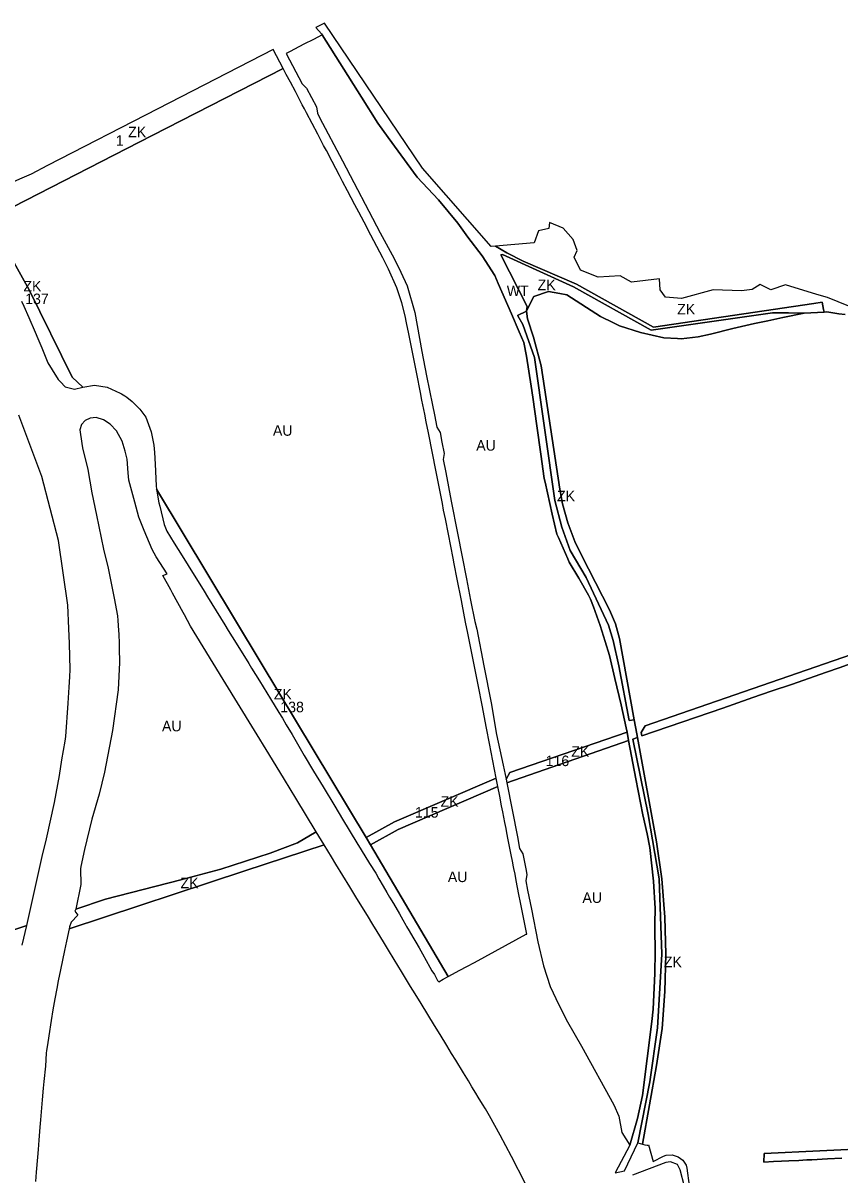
# Model space of a CAD drawing. Extents: x -521939 to -516426, y -1197857 to -1189551.
# Drawn here: x -520821 to -520047, y -1190643 to -1189551 of the extents above; entities that cross this region are included whole.
import ezdxf

# ---------------------------------------------------------------- set-up
doc = ezdxf.new("R2010")
doc.units = 0
for name, color, linetype in [('90640013', 7, 'Continuous'), ('90670013', 7, 'Continuous'), ('90710013', 7, 'Continuous'), ('90710023', 7, 'Continuous'), ('90750013', 7, 'Continuous'), ('90760013', 7, 'Continuous'), ('ID_navrh', 7, 'Continuous')]:
    doc.layers.add(name, color=color, linetype=linetype)

msp = doc.modelspace()

# ---------------------------------------------------------------- linework, layer by layer
at = {"layer": '90640013'}
msp.add_lwpolyline([(-520249.16, -1190222.86), (-520247.81, -1190230.86), (-520240.81, -1190266.98), (-520234.02, -1190301.08), (-520229.98, -1190319.14), (-520227.7, -1190332.07), (-520224.06, -1190364.1), (-520222.52, -1190389.87), (-520222.95, -1190404.31), (-520222.72, -1190408.83), (-520222.42, -1190430.62), (-520222.94, -1190451.62), (-520224.3, -1190485.28), (-520225.71, -1190497.03), (-520234.45, -1190567.4), (-520239.1, -1190588.96), (-520246.6, -1190614.37), (-520260.36, -1190640.4), (-520251.47, -1190638.58), (-520245.17, -1190625.39), (-520238.87, -1190612.21), (-520227.65, -1190554.34), (-520220.13, -1190502.96), (-520216.05, -1190433.23), (-520218.73, -1190361.97), (-520229.18, -1190300.77), (-520243.7, -1190229.44), (-520239.31, -1190227.93), (-520239.93, -1190224.53), (-520242.33, -1190211.29), (-520247.17, -1190211.76), (-520256.93, -1190159.92), (-520262.41, -1190136.08), (-520266.75, -1190121.3), (-520287.85, -1190076.23), (-520303.14, -1190050.73), (-520311.05, -1190028.55), (-520317.52, -1190003.34), (-520336.9, -1189867.83), (-520347.8, -1189836.47), (-520352.51, -1189828.3), (-520352.79, -1189827.82), (-520344.45, -1189823.72), (-520344.5, -1189823.36), (-520344.13, -1189821.36), (-520343.76, -1189819.36), (-520368.53, -1189770.54), (-520367.2, -1189770.07), (-520299.91, -1189800.71), (-520226.2, -1189841.93), (-520111.39, -1189825.49), (-520096.34, -1189825.53), (-520081.3, -1189825.57), (-520062.45, -1189824.69), (-520063.06, -1189822.2), (-520064.26, -1189815.41), (-520072.16, -1189816.57), (-520223.99, -1189839), (-520296.88, -1189798.09), (-520347.45, -1189776.56), (-520363.05, -1189768.61), (-520373.58, -1189762.19), (-520377.81, -1189762.57), (-520442.97, -1189688.4), (-520535.72, -1189550.71), (-520541.98, -1189553.93), (-520543.9, -1189554.92), (-520538.7, -1189561.06), (-520538.07, -1189562.04), (-520500.57, -1189620.82), (-520485.08, -1189645.55), (-520475.34, -1189659.1), (-520448.02, -1189696.82), (-520427.67, -1189718.16), (-520409.45, -1189740.47), (-520399.82, -1189753.72), (-520386.38, -1189771.5), (-520374.37, -1189789.92), (-520371.11, -1189797.47), (-520358.66, -1189826.35), (-520351.31, -1189843.38), (-520346.91, -1189853.63), (-520344.39, -1189866.49), (-520339.95, -1189895.05), (-520338.49, -1189905.37), (-520334.63, -1189932.46), (-520330.78, -1189959.3), (-520327.48, -1189982.3), (-520326.69, -1189985.96), (-520320.21, -1190016.34), (-520315.66, -1190035.24), (-520314.17, -1190038.32), (-520305.36, -1190058.45), (-520303.92, -1190061.74), (-520294.93, -1190077), (-520285.54, -1190093.03), (-520283.85, -1190096.73), (-520280.91, -1190104.08), (-520274.49, -1190121.75), (-520269.75, -1190136.9), (-520265.74, -1190150.19), (-520260.67, -1190171.89), (-520254.69, -1190197.09), (-520249.83, -1190218.86), (-520249.16, -1190222.86)], dxfattribs=at)
at = {"layer": '90670013'}
msp.add_lwpolyline([(-520194.85, -1190653.37), (-520198.74, -1190637.77), (-520201.28, -1190632.52), (-520208.07, -1190630.09), (-520212.3, -1190630.74), (-520243.84, -1190642.67)], dxfattribs=at)
at = {"layer": '90710013'}
for points in [[(-520038.96, -1189819.12), (-520059.38, -1189810.98), (-520069.51, -1189807.88), (-520099.05, -1189798.82), (-520113.06, -1189803.55), (-520122.95, -1189798.51), (-520130.63, -1189803.21), (-520140.61, -1189804.59), (-520167.44, -1189803.44), (-520197.6, -1189811.81), (-520212.85, -1189810.43), (-520217.67, -1189803.44), (-520218.36, -1189793.23), (-520244.78, -1189796.37), (-520255.75, -1189790.34), (-520276.62, -1189791.67), (-520293.27, -1189784.91), (-520299.12, -1189772.69), (-520296.49, -1189766.45), (-520300.08, -1189755.79), (-520309.79, -1189745.12), (-520322.5, -1189739.84), (-520323.33, -1189745.6), (-520333.04, -1189747.75), (-520337.12, -1189758.9), (-520373.58, -1189762.19)], [(-520373.58, -1189762.19), (-520363.05, -1189768.61), (-520347.45, -1189776.56), (-520296.88, -1189798.09), (-520223.99, -1189839), (-520072.16, -1189816.57), (-520064.26, -1189815.41), (-520063.06, -1189822.2), (-520062.45, -1189824.69), (-520059.78, -1189824.56), (-520048.37, -1189826.26), (-520042.45, -1189827.13)], [(-520081.3, -1189825.57), (-520096.34, -1189825.53), (-520111.39, -1189825.49), (-520226.2, -1189841.93), (-520299.91, -1189800.71), (-520367.2, -1189770.07), (-520368.53, -1189770.54), (-520343.76, -1189819.36), (-520344.13, -1189821.36), (-520344.5, -1189823.36), (-520337.54, -1189809.96), (-520323.39, -1189805.05), (-520312.92, -1189807.08), (-520306.18, -1189808.32), (-520274.3, -1189828.86), (-520262.11, -1189834.89), (-520256.38, -1189837.74), (-520236.34, -1189843.96), (-520214.4, -1189848.97), (-520201.29, -1189849.7), (-520197.95, -1189849.92), (-520181.77, -1189848.28), (-520170.1, -1189845.48), (-520148.93, -1189840.36), (-520128.53, -1189835.63), (-520115.8, -1189832.85), (-520101.68, -1189829.78), (-520081.3, -1189825.57)], [(-520344.45, -1189823.72), (-520352.79, -1189827.82), (-520352.51, -1189828.3), (-520347.8, -1189836.47), (-520336.9, -1189867.83), (-520317.52, -1190003.34), (-520311.05, -1190028.55), (-520303.14, -1190050.73), (-520287.85, -1190076.23), (-520266.75, -1190121.3), (-520262.41, -1190136.08), (-520256.93, -1190159.92), (-520247.17, -1190211.76), (-520242.33, -1190211.29), (-520256.3, -1190134.23), (-520259.95, -1190120.15), (-520265.65, -1190106.77), (-520292.4, -1190055.03), (-520298.52, -1190042.25), (-520305.18, -1190024.57), (-520310.16, -1190006.34), (-520312.72, -1189992.41), (-520330.38, -1189875.67), (-520337.66, -1189848.36), (-520343.3, -1189831.23), (-520344.45, -1189823.72)], [(-520234.43, -1190613.3), (-520221.1, -1190538.7), (-520215.9, -1190503.61), (-520213.33, -1190468.66), (-520212.39, -1190433.21), (-520213.24, -1190398.18), (-520216.08, -1190362.02), (-520221.37, -1190326.93), (-520239.31, -1190227.93), (-520243.7, -1190229.44), (-520229.18, -1190300.77), (-520218.73, -1190361.97), (-520216.05, -1190433.23), (-520220.13, -1190502.96), (-520227.65, -1190554.34), (-520238.87, -1190612.21), (-520234.43, -1190613.3)], [(-520771.4, -1190390.62), (-520772.33, -1190392.64), (-520769.41, -1190396.26), (-520775.69, -1190402.84), (-520777.17, -1190407.4), (-520777.52, -1190409.2), (-520611.12, -1190354.42), (-520536, -1190329.69), (-520543.65, -1190317.19), (-520561.41, -1190327.8), (-520587.18, -1190337.52), (-520633.86, -1190352.67), (-520671.7, -1190362.93), (-520743.3, -1190381.21), (-520771.4, -1190390.62)], [(-520822, -1190424.77), (-520817.75, -1190406.02), (-520856.45, -1190418.91)]]:
    msp.add_lwpolyline(points, dxfattribs=at)
at = {"layer": '90710023'}
for points in [[(-520862.97, -1189741.45), (-520855.05, -1189737.39), (-520698.86, -1189657.27), (-520574.91, -1189593.69), (-520584.33, -1189575.74), (-520693.52, -1189631.98), (-520798.15, -1189685.87), (-520813.62, -1189693.84), (-520824.7, -1189698.73), (-520831.59, -1189701.76), (-520832.44, -1189702.13), (-520836.95, -1189704.12), (-520848.1, -1189709.03), (-520873.85, -1189720.38), (-520875.18, -1189722.65), (-520871.46, -1189729.85), (-520862.97, -1189741.45)], [(-520822.82, -1189814.19), (-520820.55, -1189819.14), (-520815.85, -1189829.79), (-520809.87, -1189843.72), (-520807.32, -1189849.61), (-520803.4, -1189858.68), (-520797.65, -1189872.73), (-520793.8, -1189879.57), (-520788.07, -1189888.65), (-520785.91, -1189890.86), (-520781.3, -1189895.57), (-520772.63, -1189897.76), (-520764.56, -1189895.88), (-520769.62, -1189891.18), (-520774.69, -1189886.48), (-520815.47, -1189803.6), (-520840.73, -1189757.97)], [(-520492.06, -1190329.61), (-520496.15, -1190322.74), (-520595.57, -1190157.59), (-520694.98, -1189992.45), (-520692.55, -1190005.5), (-520691.84, -1190008.79), (-520687.51, -1190025.96), (-520685.06, -1190032.49), (-520678.04, -1190043.73), (-520674.3, -1190049.78), (-520668.96, -1190058.36), (-520664.99, -1190064.75), (-520649.81, -1190089.25), (-520646.54, -1190094.49), (-520634.26, -1190114.38), (-520630.08, -1190121.08), (-520626.81, -1190126.38), (-520619.25, -1190138.59), (-520607.45, -1190157.65), (-520604.7, -1190162.17), (-520597.31, -1190174.18), (-520586.78, -1190191.32), (-520578.85, -1190204.26), (-520575.54, -1190209.65), (-520571.92, -1190216.03), (-520566.46, -1190225.16), (-520555.01, -1190244.86), (-520546, -1190259.94), (-520537.12, -1190274.8), (-520525.87, -1190293.08), (-520518.77, -1190305.18), (-520505.06, -1190327.7), (-520500.89, -1190334.53), (-520493.14, -1190347.28), (-520487.23, -1190356.63), (-520484.26, -1190361.73), (-520480.03, -1190368.97), (-520476.65, -1190374.74), (-520474.06, -1190379.19), (-520470.42, -1190385.29), (-520464.79, -1190395.13), (-520461.6, -1190400.68), (-520458.54, -1190405.84), (-520457.88, -1190406.97), (-520455.54, -1190411.02), (-520452.05, -1190417.09), (-520449.33, -1190421.77), (-520446.15, -1190427.25), (-520442.94, -1190432.82), (-520435.78, -1190445.73), (-520433.93, -1190449.11), (-520431.58, -1190452.47), (-520428.66, -1190458.29), (-520427.37, -1190459.39), (-520423.37, -1190457.05), (-520418.63, -1190454.51), (-520492.06, -1190329.61)], [(-519984.27, -1190131.37), (-520061.95, -1190158.2), (-520231.96, -1190216.92), (-520235.61, -1190223.15), (-520235.01, -1190226.44), (-520158.52, -1190200.01), (-520148.48, -1190196.56), (-520129.95, -1190190.13), (-520112.49, -1190184.08), (-520092.49, -1190177.21), (-520071.81, -1190170.12), (-520060.18, -1190166.05), (-520048.21, -1190161.91), (-520036.77, -1190157.93)], [(-520249.16, -1190222.86), (-520360.13, -1190261.18), (-520363.78, -1190267.42), (-520363.12, -1190270.76), (-520247.81, -1190230.86), (-520249.16, -1190222.86)], [(-520492.06, -1190329.61), (-520465.85, -1190315.02), (-520371.58, -1190274.42), (-520372.97, -1190266.32), (-520469.39, -1190307.83), (-520496.15, -1190322.74), (-520492.06, -1190329.61)], [(-519961.08, -1190614.58), (-520119.28, -1190622.29), (-520119.46, -1190630.32), (-520110.38, -1190629.91), (-520102.91, -1190629.55), (-520095.81, -1190629.12), (-520086.43, -1190628.7), (-520078.68, -1190628.32), (-520074.1, -1190628.1), (-520059.37, -1190627.38), (-520045.77, -1190626.72)]]:
    msp.add_lwpolyline(points, dxfattribs=at)
at = {"layer": '90750013'}
for points in [[(-520249.16, -1190222.86), (-520249.83, -1190218.86), (-520254.69, -1190197.09), (-520260.67, -1190171.89), (-520265.74, -1190150.19), (-520269.75, -1190136.9), (-520274.49, -1190121.75), (-520280.91, -1190104.08), (-520283.85, -1190096.73), (-520285.54, -1190093.03), (-520294.93, -1190077), (-520303.92, -1190061.74), (-520305.36, -1190058.45), (-520314.17, -1190038.32), (-520315.66, -1190035.24), (-520320.21, -1190016.34), (-520326.69, -1189985.96), (-520327.48, -1189982.3), (-520330.78, -1189959.3), (-520334.63, -1189932.46), (-520338.49, -1189905.37), (-520339.95, -1189895.05), (-520344.39, -1189866.49), (-520346.91, -1189853.63), (-520351.31, -1189843.38), (-520358.66, -1189826.35), (-520371.11, -1189797.47), (-520374.37, -1189789.92), (-520386.38, -1189771.5), (-520399.82, -1189753.72), (-520409.45, -1189740.47), (-520427.67, -1189718.16), (-520448.02, -1189696.82), (-520475.34, -1189659.1), (-520485.08, -1189645.55), (-520500.57, -1189620.82), (-520538.07, -1189562.04), (-520542.1, -1189564.12), (-520546.14, -1189566.2), (-520555.14, -1189570.83), (-520564.14, -1189575.47), (-520568.14, -1189577.53), (-520572.14, -1189579.59), (-520557.02, -1189608.4), (-520552.66, -1189612.4), (-520543.28, -1189630.26), (-520542.46, -1189636.12), (-520540.29, -1189640.25), (-520518.67, -1189681.41), (-520483.13, -1189749.49), (-520469.68, -1189773.95), (-520463.47, -1189786.79), (-520457.28, -1189799.95), (-520450.25, -1189825.06), (-520443.42, -1189862.15), (-520438.94, -1189885.01), (-520433.46, -1189912.89), (-520431.66, -1189922.07), (-520429.34, -1189933.8), (-520426.3, -1189938.88), (-520424.49, -1189948.09), (-520422.41, -1189958.68), (-520423.3, -1189964.53), (-520420.88, -1189976.82), (-520415.58, -1190003.82), (-520409.61, -1190034.24), (-520405.21, -1190056.77), (-520401.22, -1190077.65), (-520397.27, -1190097.65), (-520393.2, -1190117.89), (-520391.56, -1190125.16), (-520384.87, -1190160.07), (-520377.99, -1190195.02), (-520372.66, -1190225.12), (-520366.37, -1190254.23), (-520363.78, -1190267.42), (-520360.13, -1190261.18), (-520249.16, -1190222.86)], [(-520372.97, -1190266.32), (-520379.42, -1190233.48), (-520382.22, -1190219.18), (-520386.49, -1190197.4), (-520389.99, -1190179.56), (-520393.44, -1190162.05), (-520398.08, -1190138.46), (-520400.22, -1190127.57), (-520401.68, -1190120.11), (-520402.94, -1190113.68), (-520405.98, -1190098.21), (-520409.99, -1190077.75), (-520412.81, -1190063.42), (-520413.93, -1190058), (-520418.36, -1190035.16), (-520421.24, -1190020.5), (-520422.85, -1190012.32), (-520424.06, -1190006.15), (-520428.73, -1189982.35), (-520429.98, -1189976.03), (-520437.33, -1189939.01), (-520439.37, -1189928.74), (-520440.81, -1189921.53), (-520443.47, -1189908.13), (-520444.85, -1189900.94), (-520448.32, -1189883.37), (-520448.96, -1189880.06), (-520452.13, -1189864.14), (-520455.88, -1189845.31), (-520457.93, -1189834.89), (-520459.4, -1189828.36), (-520462.52, -1189816.05), (-520467.22, -1189801.74), (-520474.96, -1189783.97), (-520478.5, -1189777.12), (-520480.47, -1189773.36), (-520491.89, -1189751.79), (-520498.25, -1189739.55), (-520503.29, -1189730.03), (-520506.96, -1189723.04), (-520513.98, -1189709.68), (-520518.55, -1189700.78), (-520521.58, -1189695.28), (-520528.55, -1189681.89), (-520533.97, -1189671.56), (-520536.5, -1189666.75), (-520542.06, -1189656.2), (-520552.78, -1189635.77), (-520554.77, -1189631.94), (-520556.78, -1189628.12), (-520563.29, -1189615.69), (-520567.98, -1189606.88), (-520571.87, -1189599.49), (-520574.91, -1189593.69), (-520698.86, -1189657.27), (-520855.05, -1189737.39)], [(-520840.73, -1189757.97), (-520815.47, -1189803.6), (-520774.69, -1189886.48), (-520769.62, -1189891.18), (-520764.56, -1189895.88), (-520753.69, -1189893.86), (-520741.72, -1189895.94), (-520729.38, -1189901.54), (-520727.89, -1189902.2), (-520724.92, -1189904.07), (-520722.93, -1189905.34), (-520717.89, -1189909.3), (-520710.73, -1189916.79), (-520704.82, -1189924.14), (-520699.84, -1189938.24), (-520697.31, -1189950.87), (-520696.76, -1189957.88), (-520696, -1189968.88), (-520695.16, -1189989.28), (-520694.98, -1189992.45), (-520595.57, -1190157.59), (-520496.15, -1190322.74), (-520469.39, -1190307.83), (-520372.97, -1190266.32)], [(-520042.45, -1189827.13), (-520048.37, -1189826.26), (-520059.78, -1189824.56), (-520062.45, -1189824.69), (-520081.3, -1189825.57), (-520101.68, -1189829.78), (-520115.8, -1189832.85), (-520128.53, -1189835.63), (-520148.93, -1189840.36), (-520170.1, -1189845.48), (-520181.77, -1189848.28), (-520197.95, -1189849.92), (-520201.29, -1189849.7), (-520214.4, -1189848.97), (-520236.34, -1189843.96), (-520256.38, -1189837.74), (-520262.11, -1189834.89), (-520274.3, -1189828.86), (-520306.18, -1189808.32), (-520312.92, -1189807.08), (-520323.39, -1189805.05), (-520337.54, -1189809.96), (-520344.5, -1189823.36), (-520344.45, -1189823.72), (-520343.3, -1189831.23), (-520337.66, -1189848.36), (-520330.38, -1189875.67), (-520312.72, -1189992.41), (-520310.16, -1190006.34), (-520305.18, -1190024.57), (-520298.52, -1190042.25), (-520292.4, -1190055.03), (-520265.65, -1190106.77), (-520259.95, -1190120.15), (-520256.3, -1190134.23), (-520242.33, -1190211.29), (-520239.93, -1190224.53), (-520239.31, -1190227.93), (-520221.37, -1190326.93), (-520216.08, -1190362.02), (-520213.24, -1190398.18), (-520212.39, -1190433.21), (-520213.33, -1190468.66), (-520215.9, -1190503.61), (-520221.1, -1190538.7), (-520234.43, -1190613.3)], [(-520771.4, -1190390.62), (-520743.3, -1190381.21), (-520671.7, -1190362.93), (-520633.86, -1190352.67), (-520587.18, -1190337.52), (-520561.41, -1190327.8), (-520543.65, -1190317.19), (-520562.95, -1190285.42), (-520573.64, -1190267.85), (-520588.57, -1190243.38), (-520602.03, -1190221.27), (-520631.58, -1190172.83), (-520650.61, -1190142), (-520662.54, -1190122.49), (-520668.3, -1190111.67), (-520669.52, -1190109.47), (-520679.67, -1190091.18), (-520681.36, -1190087.92), (-520688.71, -1190074.44), (-520684.77, -1190072.63), (-520695.03, -1190056.68), (-520698.97, -1190049.7), (-520706.59, -1190031.62), (-520711.57, -1190019.13), (-520715.35, -1190004.73), (-520721.1, -1189984.1), (-520721.7, -1189976.9), (-520722.75, -1189964.15), (-520724.42, -1189956.39), (-520727.49, -1189947.13), (-520732.65, -1189937.29), (-520738.61, -1189931.05), (-520745.07, -1189926.77), (-520751.84, -1189924.64), (-520757.73, -1189925.33), (-520762.53, -1189927.5), (-520766.03, -1189931.34), (-520767.38, -1189936.19), (-520765.67, -1189949.12), (-520765.09, -1189953.48), (-520759.8, -1189973.83), (-520756.09, -1189995.85), (-520751.63, -1190017.23), (-520745.18, -1190049.33), (-520740.47, -1190067.29), (-520734.91, -1190095.84), (-520731.89, -1190112.51), (-520731.61, -1190116.98), (-520730.74, -1190126.36), (-520730.51, -1190129.92), (-520730.21, -1190138.71), (-520730.06, -1190143.1), (-520730.03, -1190156.85), (-520731.14, -1190182.68), (-520736.44, -1190221.23), (-520744.03, -1190260.62), (-520749.23, -1190281.66), (-520755.95, -1190305.31), (-520763.12, -1190334.1), (-520766.67, -1190350.13), (-520766.88, -1190352.45), (-520766.57, -1190367.27), (-520771.4, -1190390.62)], [(-520036.77, -1190157.93), (-520048.21, -1190161.91), (-520060.18, -1190166.05), (-520071.81, -1190170.12), (-520092.49, -1190177.21), (-520112.49, -1190184.08), (-520129.95, -1190190.13), (-520148.48, -1190196.56), (-520158.52, -1190200.01), (-520235.01, -1190226.44), (-520235.61, -1190223.15), (-520231.96, -1190216.92), (-520061.95, -1190158.2), (-519984.27, -1190131.37)], [(-520363.12, -1190270.76), (-520352.86, -1190322.18), (-520350.9, -1190332.99), (-520347.86, -1190338.07), (-520345.06, -1190352.29), (-520343.97, -1190357.86), (-520344.85, -1190363.88), (-520343.5, -1190372.52), (-520339.48, -1190390.73), (-520333.62, -1190421.51), (-520328.19, -1190444.19), (-520322.01, -1190463.84), (-520313.7, -1190481.31), (-520305.38, -1190497.4), (-520292.37, -1190520.37), (-520261.73, -1190576.17), (-520256.94, -1190586.97), (-520254.03, -1190602.44), (-520246.6, -1190614.37), (-520239.1, -1190588.96), (-520234.45, -1190567.4), (-520225.71, -1190497.03), (-520224.3, -1190485.28), (-520222.94, -1190451.62), (-520222.42, -1190430.62), (-520222.72, -1190408.83), (-520222.95, -1190404.31), (-520222.52, -1190389.87), (-520224.06, -1190364.1), (-520227.7, -1190332.07), (-520229.98, -1190319.14), (-520234.02, -1190301.08), (-520240.81, -1190266.98), (-520247.81, -1190230.86), (-520363.12, -1190270.76)], [(-520492.06, -1190329.61), (-520418.63, -1190454.51), (-520407.42, -1190448.5), (-520400.84, -1190444.97), (-520393.65, -1190441.07), (-520344.6, -1190414.44), (-520344.11, -1190414.17), (-520345.34, -1190407.94), (-520346.85, -1190400.25), (-520349.98, -1190384.24), (-520351.48, -1190376.69), (-520352.77, -1190370.15), (-520354.1, -1190363.35), (-520355.24, -1190357.44), (-520356.28, -1190352.2), (-520356.65, -1190350.44), (-520357.64, -1190345.16), (-520358.8, -1190339.19), (-520361.67, -1190324.78), (-520362.96, -1190318.16), (-520363.75, -1190314.16), (-520364.88, -1190308.35), (-520366.87, -1190298.24), (-520368, -1190292.59), (-520369.76, -1190283.42), (-520371.58, -1190274.42), (-520465.85, -1190315.02), (-520492.06, -1190329.61)], [(-520345.65, -1190650.45), (-520358.66, -1190624.95), (-520369.41, -1190604.73), (-520379.45, -1190586.67), (-520383.32, -1190580.03), (-520385.97, -1190575.6), (-520390.09, -1190568.79), (-520392.43, -1190564.91), (-520396.02, -1190558.98), (-520399.35, -1190553.5), (-520403.94, -1190545.91), (-520411.44, -1190533.73), (-520415.33, -1190527.35), (-520419.93, -1190519.84), (-520426.27, -1190509.45), (-520431.56, -1190500.75), (-520444.12, -1190480.2), (-520449.8, -1190470.9), (-520454.13, -1190463.8), (-520462.71, -1190449.78), (-520469.77, -1190438.2), (-520475.02, -1190429.58), (-520479.82, -1190421.71), (-520485.87, -1190411.78), (-520489.99, -1190405.05), (-520495.11, -1190396.67), (-520504.99, -1190380.53), (-520511.82, -1190369.31), (-520524.85, -1190347.98), (-520529.17, -1190340.88), (-520536, -1190329.69), (-520611.12, -1190354.42), (-520777.52, -1190409.2), (-520780.24, -1190420.99), (-520782.1, -1190429.75), (-520785.71, -1190448.27), (-520787.86, -1190458.71), (-520789.3, -1190465.75), (-520791.14, -1190475.72), (-520792.99, -1190486.07), (-520794.61, -1190496.02), (-520796.96, -1190510.64), (-520798.24, -1190519.38), (-520799.02, -1190524.64), (-520799.22, -1190527.06), (-520800.12, -1190539.43), (-520801.46, -1190554.11), (-520802.05, -1190560.34), (-520803.12, -1190571.38), (-520804.73, -1190590.26), (-520805.28, -1190597.35), (-520806.21, -1190609.49), (-520806.79, -1190618.32), (-520807.44, -1190625.67), (-520808.7, -1190640.05), (-520809.38, -1190648.62)], [(-520234.43, -1190613.3), (-520232.21, -1190613.85), (-520229.99, -1190614.4), (-520229.32, -1190614.25), (-520228.66, -1190614.1), (-520226.49, -1190621.92), (-520224.31, -1190629.74), (-520214.66, -1190624.69), (-520211.94, -1190623.66), (-520206.24, -1190623.53), (-520200.85, -1190625.24), (-520196.31, -1190628.66), (-520193.15, -1190633.39), (-520192.44, -1190636.14), (-520190.15, -1190652.41)], [(-520045.77, -1190626.72), (-520059.37, -1190627.38), (-520074.1, -1190628.1), (-520078.68, -1190628.32), (-520086.43, -1190628.7), (-520095.81, -1190629.12), (-520102.91, -1190629.55), (-520110.38, -1190629.91), (-520119.46, -1190630.32), (-520119.28, -1190622.29), (-519961.08, -1190614.58)]]:
    msp.add_lwpolyline(points, dxfattribs=at)
at = {"layer": '90760013'}
msp.add_lwpolyline([(-520856.45, -1190418.91), (-520817.75, -1190406.02), (-520803.11, -1190340.79), (-520799.14, -1190323.82), (-520791.44, -1190289.68), (-520786.83, -1190263.81), (-520784.36, -1190249.11), (-520781.3, -1190231.43), (-520780.79, -1190226.94), (-520778.53, -1190195.44), (-520777.49, -1190180.07), (-520776.83, -1190170.44), (-520776.47, -1190163.36), (-520777.29, -1190138.74), (-520777.95, -1190124.57), (-520778.83, -1190102.4), (-520787.67, -1190041.34), (-520803.36, -1189980.65), (-520825.3, -1189922.44)], dxfattribs=at)

# ---------------------------------------------------------------- texts
at = {"layer": '90640013'}
msp.add_text('WT', height=10, rotation=360, dxfattribs=at).set_placement((-520363.07, -1189809.51))
at = {"layer": '90710013'}
for rotation, p in [(0, (-520333.82, -1189803.92)), (360, (-520201.67, -1189826.92)), (0, (-520315.46, -1190003.99)), (0, (-520672.1, -1190370.8)), (0, (-520214.34, -1190445.63))]:
    msp.add_text('ZK', height=10, rotation=rotation, dxfattribs=at).set_placement(p)
at = {"layer": '90710023'}
for rotation, p in [(0, (-520721.72, -1189658.94)), (360, (-520820.92, -1189805.1)), (0, (-520583.77, -1190191.85)), (360, (-520301.96, -1190246.2)), (360, (-520425.76, -1190293.61))]:
    msp.add_text('ZK', height=10, rotation=rotation, dxfattribs=at).set_placement(p)
at = {"layer": '90750013'}
for rotation, p in [(0, (-520584.54, -1189941.9)), (0, (-520391.98, -1189956.05)), (0, (-520689.64, -1190222.08)), (360, (-520418.88, -1190364.97)), (360, (-520291.39, -1190384.71))]:
    msp.add_text('AU', height=10, rotation=rotation, dxfattribs=at).set_placement(p)
at = {"layer": 'ID_navrh'}
for s, rotation, p in [('1', 0, (-520733.41, -1189667.06)), ('137', 0, (-520819.23, -1189817.15)), ('138', 360, (-520577.55, -1190204)), ('116', 0, (-520326.21, -1190255.05)), ('115', 0, (-520450.01, -1190303.87))]:
    msp.add_text(s, height=10, rotation=rotation, dxfattribs=at).set_placement(p)

doc.saveas('drawing.dxf')
